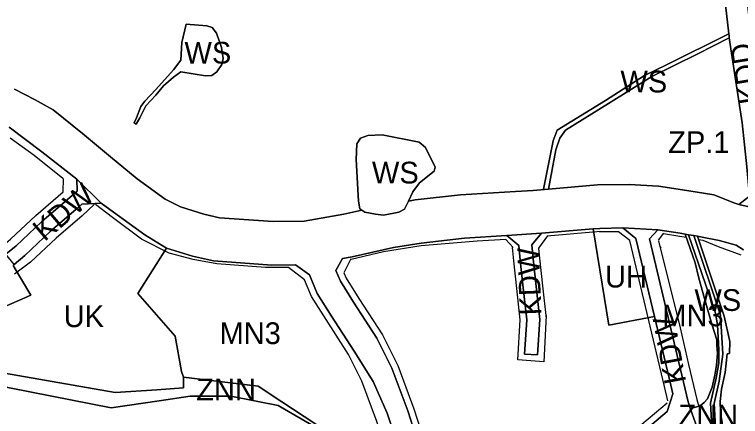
# Model space of a CAD drawing. Extents: x 7417187 to 7419415, y 5539178 to 5540826.
# Drawn here: x 7418734.7 to 7419069, y 5539661.6 to 5539846.6 of the extents above; entities that cross this region are included whole.
import ezdxf

# ---------------------------------------------------------------- set-up
doc = ezdxf.new("R2010")
doc.units = 0
for name, color, linetype in [('linie_rozgraniczajace', 7, 'Continuous'), ('linie_zabudowy_nieprzekraczalne', 7, 'Continuous'), ('oznaczenia_przeznaczen', 7, 'Continuous')]:
    doc.layers.add(name, color=color, linetype=linetype)

msp = doc.modelspace()

# ---------------------------------------------------------------- linework, layer by layer
at = {"layer": 'linie_rozgraniczajace'}
for p, q in [((7418734.61, 5539812.19), (7418744.21, 5539807.3)), ((7418744.21, 5539807.3), (7418752.52, 5539802.7)), ((7418752.52, 5539802.7), (7418766.03, 5539791.85)), ((7418747.18, 5539783.41), (7418732.26, 5539794.78)), ((7418766.03, 5539791.85), (7418778.84, 5539781.11)), ((7418763.35, 5539770.81), (7418747.18, 5539783.41)), ((7418778.84, 5539781.11), (7418791.15, 5539770.95)), ((7418774.51, 5539759.77), (7418763.35, 5539770.81)), ((7418791.15, 5539770.95), (7418804.08, 5539761.58)), ((7418980.62, 5539766.28), (7419003.17, 5539768.16)), ((7419003.17, 5539768.16), (7419017.77, 5539768.42)), ((7419017.77, 5539768.42), (7419031.26, 5539767.62)), ((7419031.26, 5539767.62), (7419044.35, 5539765.68)), ((7418940.11, 5539763.69), (7418965.45, 5539765.2)), ((7418965.45, 5539765.2), (7418973.52, 5539765.68)), ((7418973.52, 5539765.68), (7418978.79, 5539766.12)), ((7418978.79, 5539766.12), (7418980.62, 5539766.28)), ((7419044.35, 5539765.68), (7419056.75, 5539763.59)), ((7418804.08, 5539761.58), (7418811.03, 5539758.06)), ((7418914.35, 5539757.03), (7418916.12, 5539760.75)), ((7418916.12, 5539760.75), (7418919.26, 5539761.26)), ((7418919.26, 5539761.26), (7418940.11, 5539763.69)), ((7419056.75, 5539763.59), (7419066.42, 5539759.83)), ((7418780.23, 5539755.6), (7418774.51, 5539759.77)), ((7418811.03, 5539758.06), (7418821.83, 5539754.66)), ((7419066.42, 5539759.83), (7419068.31, 5539759.14)), ((7419068.31, 5539759.14), (7419081.09, 5539756.29)), ((7418794.71, 5539745.18), (7418780.23, 5539755.6)), ((7418821.83, 5539754.66), (7418829.13, 5539753.05)), ((7418868.04, 5539751.48), (7418886.3, 5539754.76)), ((7418886.3, 5539754.76), (7418894.56, 5539756.6)), ((7418894.56, 5539756.6), (7418895.99, 5539755.69)), ((7418895.99, 5539755.69), (7418900.98, 5539754.68)), ((7418900.98, 5539754.68), (7418904.59, 5539754.27)), ((7418904.59, 5539754.27), (7418911.62, 5539755.68)), ((7418911.62, 5539755.68), (7418914.35, 5539757.03)), ((7418829.13, 5539753.05), (7418853.81, 5539751.33)), ((7418853.81, 5539751.33), (7418868.04, 5539751.48)), ((7419001.16, 5539747.92), (7418977.42, 5539745.94)), ((7419004.18, 5539748.18), (7419001.16, 5539747.92)), ((7419014.82, 5539748.37), (7419004.18, 5539748.18)), ((7419030.91, 5539747.46), (7419014.82, 5539748.37)), ((7419041.22, 5539745.93), (7419030.91, 5539747.46)), ((7418804.62, 5539739.12), (7418794.71, 5539745.18)), ((7418961.45, 5539744.93), (7418941.87, 5539743.76)), ((7418977.42, 5539745.94), (7418961.45, 5539744.93)), ((7419043.55, 5539745.53), (7419041.22, 5539745.93)), ((7419045.02, 5539745.28), (7419043.55, 5539745.53)), ((7419047.5, 5539744.86), (7419045.02, 5539745.28)), ((7419049.17, 5539744.58), (7419047.5, 5539744.86)), ((7419051.4, 5539744.21), (7419049.17, 5539744.58)), ((7419059.26, 5539742.54), (7419051.4, 5539744.21)), ((7418922.01, 5539741.44), (7418909.26, 5539739.38)), ((7418941.87, 5539743.76), (7418922.01, 5539741.44)), ((7419066.99, 5539740.46), (7419059.26, 5539742.54)), ((7418816.66, 5539735.33), (7418804.62, 5539739.12)), ((7418909.26, 5539739.38), (7418890.24, 5539735.15)), ((7419070.47, 5539738.34), (7419066.99, 5539740.46)), ((7418826.26, 5539733.2), (7418816.66, 5539735.33)), ((7418885.72, 5539734.33), (7418882.61, 5539728.84)), ((7418890.24, 5539735.15), (7418885.72, 5539734.33)), ((7418853.21, 5539731.33), (7418826.26, 5539733.2)), ((7418864.01, 5539731.44), (7418853.21, 5539731.33)), ((7418870.47, 5539726.74), (7418864.01, 5539731.44)), ((7418882.61, 5539728.84), (7418884.73, 5539723.85)), ((7418874.06, 5539718.28), (7418870.47, 5539726.74)), ((7418884.73, 5539723.85), (7418890.76, 5539714.26)), ((7418880.65, 5539707.8), (7418874.06, 5539718.28)), ((7418890.76, 5539714.26), (7418901.58, 5539697.65)), ((7418891.15, 5539691.67), (7418880.65, 5539707.8)), ((7418901.58, 5539697.65), (7418908.47, 5539683.84)), ((7418899.89, 5539677.74), (7418891.15, 5539691.67)), ((7418908.47, 5539683.84), (7418915.76, 5539664.18)), ((7418906.24, 5539663.18), (7418899.89, 5539677.74)), ((7418915.76, 5539664.18), (7418920.06, 5539650.87)), ((7418910.1, 5539651.81), (7418906.24, 5539663.18))]:
    msp.add_line(p, q, dxfattribs=at)
for points in [[(7419061.66, 5539855.14), (7419063.63, 5539837.78), (7419034.92, 5539823.52), (7419024.87, 5539818.62), (7419006.8, 5539807.01), (7418984.61, 5539793.4), (7418982.8, 5539788.45), (7418978.36, 5539766.3), (7418978.79, 5539766.12), (7418973.52, 5539765.68), (7418965.45, 5539765.2), (7418940.11, 5539763.69), (7418919.26, 5539761.26), (7418916.12, 5539760.75), (7418918.11, 5539764.97), (7418921.2, 5539769.2), (7418927.98, 5539774.45), (7418928.33, 5539776.42), (7418923.97, 5539785.48), (7418921.07, 5539787.94), (7418903.96, 5539791.29), (7418897.36, 5539790.98), (7418894.02, 5539789.68), (7418892.37, 5539787.04), (7418892.01, 5539779.82), (7418893.08, 5539760.72), (7418893.7, 5539757.14), (7418894.56, 5539756.6), (7418886.3, 5539754.76), (7418868.04, 5539751.48), (7418853.81, 5539751.33), (7418829.13, 5539753.05), (7418821.83, 5539754.66), (7418811.03, 5539758.06), (7418804.08, 5539761.58), (7418791.15, 5539770.95), (7418778.84, 5539781.11), (7418766.03, 5539791.85), (7418752.52, 5539802.7), (7418744.21, 5539807.3), (7418734.61, 5539812.19)], [(7419071.59, 5539856.29), (7419073.67, 5539837.92), (7419076.8, 5539817.26), (7419079.76, 5539798.03), (7419081.88, 5539777.49), (7419082.92, 5539766.9), (7419083.42, 5539761.8), (7419083.36, 5539760.85), (7419087.96, 5539754.81), (7419081.09, 5539756.29), (7419068.31, 5539759.14), (7419073.25, 5539763.02), (7419071.93, 5539776.49), (7419069.84, 5539796.75), (7419066.92, 5539815.75), (7419063.87, 5539835.91), (7419063.76, 5539836.61), (7419063.63, 5539837.78), (7419061.66, 5539855.14)], [(7418732.26, 5539794.78), (7418747.18, 5539783.41), (7418763.35, 5539770.81), (7418763.48, 5539765.38), (7418759.1, 5539761.43), (7418747.12, 5539751.15), (7418735.44, 5539740.18), (7418730.71, 5539736.26)], [(7418920.06, 5539650.87), (7418915.76, 5539664.18), (7418908.47, 5539683.84), (7418901.58, 5539697.65), (7418890.76, 5539714.26), (7418884.73, 5539723.85), (7418882.61, 5539728.84), (7418885.72, 5539734.33), (7418890.24, 5539735.15), (7418909.26, 5539739.38), (7418922.01, 5539741.44), (7418941.87, 5539743.76), (7418961.45, 5539744.93), (7418966.91, 5539740.25), (7418967.54, 5539733.52), (7418968.92, 5539720.8), (7418970.59, 5539706.17), (7418969.57, 5539690.33), (7418975.55, 5539689.94), (7418976.62, 5539706.32), (7418974.88, 5539721.46), (7418973.51, 5539734.12), (7418972.91, 5539740.55), (7418977.42, 5539745.94), (7419001.16, 5539747.92), (7419008.35, 5539703.62), (7419029.46, 5539707.58), (7419036.97, 5539676.03), (7419037.87, 5539672.08), (7419035.19, 5539663.96), (7419023.09, 5539653.63)], [(7419023.09, 5539653.63), (7419035.19, 5539663.96), (7419037.87, 5539672.08), (7419036.97, 5539676.03), (7419029.46, 5539707.58), (7419020.89, 5539743.57), (7419014.82, 5539748.37), (7419030.91, 5539747.46), (7419027.12, 5539743.33), (7419042.81, 5539677.39), (7419044.89, 5539668.35), (7419045.89, 5539665.52), (7419049.14, 5539656.4)], [(7419049.14, 5539656.4), (7419045.89, 5539665.52), (7419046.75, 5539665.51), (7419050.45, 5539666.45), (7419052.24, 5539668.1), (7419053.83, 5539669.81), (7419056.05, 5539675.14), (7419057.26, 5539680.71), (7419057.94, 5539685.19), (7419058.5, 5539690.67), (7419058.14, 5539694.46), (7419058.1, 5539696.97), (7419055.88, 5539704.12), (7419052.45, 5539715.97), (7419049.85, 5539725.26), (7419048.08, 5539732.41), (7419043.55, 5539745.53), (7419045.02, 5539745.28), (7419057.49, 5539709.17), (7419058.46, 5539703.84), (7419059.04, 5539692.28), (7419059.02, 5539686.28), (7419057.85, 5539679.27), (7419055.16, 5539667.82), (7419055.93, 5539654.12)], [(7419057.67, 5539654.15), (7419056.87, 5539667.66), (7419059.26, 5539677.84), (7419060.96, 5539690.25), (7419059.78, 5539708.29), (7419047.5, 5539744.86), (7419049.17, 5539744.58), (7419061.52, 5539707.82), (7419064.17, 5539696.06), (7419064.03, 5539690.68), (7419062.96, 5539690.49), (7419062.02, 5539681.91), (7419060.32, 5539674.24), (7419059.62, 5539668.54), (7419059.89, 5539663.67), (7419062.14, 5539648.91)], [(7419062.14, 5539648.91), (7419059.89, 5539663.67), (7419059.62, 5539668.54), (7419060.32, 5539674.24), (7419062.02, 5539681.91), (7419062.96, 5539690.49), (7419064.03, 5539690.68), (7419064.17, 5539696.06), (7419061.52, 5539707.82), (7419049.17, 5539744.58), (7419051.4, 5539744.21), (7419059.26, 5539742.54), (7419066.99, 5539740.46), (7419070.47, 5539738.34)], [(7418734.05, 5539731.09), (7418742.1, 5539717.38), (7418736.92, 5539715.13), (7418726.22, 5539710.49)], [(7418716.69, 5539683.83), (7418781.07, 5539672.68), (7418800.26, 5539673.95), (7418812.43, 5539674.88), (7418812.55, 5539679.73), (7418846.8, 5539675.56), (7418857.8, 5539668.36), (7418872.9, 5539658.41), (7418881.51, 5539653.71), (7418890.59, 5539644.9), (7418897.27, 5539634.04), (7418892.9, 5539630.28), (7418888.03, 5539643.41), (7418871.51, 5539657.77), (7418856.13, 5539666.67), (7418834.34, 5539671.03), (7418815.62, 5539670.95), (7418801.32, 5539668.85), (7418779.1, 5539665.63), (7418723.54, 5539676.5)], [(7418723.54, 5539676.5), (7418779.1, 5539665.63), (7418801.32, 5539668.85), (7418815.62, 5539670.95), (7418834.34, 5539671.03), (7418856.13, 5539666.67), (7418871.51, 5539657.77)]]:
    msp.add_lwpolyline(points, dxfattribs=at)
for points in [[(7418830.19, 5539823.65), (7418827.84, 5539820.26), (7418825.49, 5539818.54), (7418822.57, 5539818.36), (7418811.24, 5539820.26), (7418807.88, 5539817.8), (7418803.3, 5539813.86), (7418799.81, 5539809.56), (7418795.17, 5539804.53), (7418792.33, 5539799.07), (7418790.67, 5539796.14), (7418789.75, 5539796.79), (7418790.84, 5539799.11), (7418792.81, 5539804.23), (7418794.68, 5539806.78), (7418799.71, 5539812.13), (7418807.85, 5539821.16), (7418811.21, 5539825.62), (7418811.76, 5539833.67), (7418813.64, 5539842.14), (7418823.19, 5539841.41), (7418825.64, 5539840.63), (7418827.62, 5539837.97), (7418829.94, 5539831.47), (7418830.83, 5539826.34)], [(7418830.19, 5539823.65), (7418830.83, 5539826.34), (7418829.94, 5539831.47), (7418827.62, 5539837.97), (7418825.64, 5539840.63), (7418823.19, 5539841.41), (7418813.64, 5539842.14), (7418811.76, 5539833.67), (7418811.21, 5539825.62), (7418807.85, 5539821.16), (7418799.71, 5539812.13), (7418794.68, 5539806.78), (7418792.81, 5539804.23), (7418790.84, 5539799.11), (7418789.75, 5539796.79), (7418790.67, 5539796.14), (7418792.33, 5539799.07), (7418795.17, 5539804.53), (7418799.81, 5539809.56), (7418803.3, 5539813.86), (7418807.88, 5539817.8), (7418811.24, 5539820.26), (7418822.57, 5539818.36), (7418825.49, 5539818.54), (7418827.84, 5539820.26)], [(7419063.87, 5539835.91), (7419049.32, 5539828.49), (7419028.14, 5539818.06), (7419008.25, 5539805.73), (7418988.47, 5539793.43), (7418985.78, 5539789.71), (7418983.98, 5539784.4), (7418980.62, 5539766.28), (7418978.79, 5539766.12), (7418978.36, 5539766.3), (7418982.8, 5539788.45), (7418984.61, 5539793.4), (7419006.8, 5539807.01), (7419024.87, 5539818.62), (7419034.92, 5539823.52), (7419063.63, 5539837.78), (7419063.76, 5539836.61)], [(7419068.31, 5539759.14), (7419066.42, 5539759.83), (7419056.75, 5539763.59), (7419044.35, 5539765.68), (7419031.26, 5539767.62), (7419017.77, 5539768.42), (7419003.17, 5539768.16), (7418980.62, 5539766.28), (7418983.98, 5539784.4), (7418985.78, 5539789.71), (7418988.47, 5539793.43), (7419008.25, 5539805.73), (7419028.14, 5539818.06), (7419049.32, 5539828.49), (7419063.87, 5539835.91), (7419066.92, 5539815.75), (7419069.84, 5539796.75), (7419071.93, 5539776.49), (7419073.25, 5539763.02)], [(7418916.12, 5539760.75), (7418914.35, 5539757.03), (7418911.62, 5539755.68), (7418904.59, 5539754.27), (7418900.98, 5539754.68), (7418895.99, 5539755.69), (7418894.56, 5539756.6), (7418893.7, 5539757.14), (7418893.08, 5539760.72), (7418892.01, 5539779.82), (7418892.37, 5539787.04), (7418894.02, 5539789.68), (7418897.36, 5539790.98), (7418903.96, 5539791.29), (7418921.07, 5539787.94), (7418923.97, 5539785.48), (7418928.33, 5539776.42), (7418927.98, 5539774.45), (7418921.2, 5539769.2), (7418918.11, 5539764.97)], [(7418774.51, 5539759.77), (7418765.61, 5539759.3), (7418763.11, 5539756.96), (7418751.12, 5539746.68), (7418739.41, 5539735.68), (7418734.54, 5539731.64), (7418730.71, 5539736.26), (7418735.44, 5539740.18), (7418747.12, 5539751.15), (7418759.1, 5539761.43), (7418763.48, 5539765.38), (7418763.35, 5539770.81)], [(7418804.62, 5539739.12), (7418791.51, 5539718.25), (7418808.62, 5539698.53), (7418811.52, 5539682.26), (7418812.55, 5539679.73), (7418812.43, 5539674.88), (7418800.26, 5539673.95), (7418781.07, 5539672.68), (7418716.69, 5539683.83), (7418704.53, 5539706.68), (7418719.32, 5539708.39), (7418725.09, 5539710), (7418726.22, 5539710.49), (7418736.92, 5539715.13), (7418742.1, 5539717.38), (7418734.05, 5539731.09), (7418734.54, 5539731.64), (7418739.41, 5539735.68), (7418751.12, 5539746.68), (7418763.11, 5539756.96), (7418765.61, 5539759.3), (7418774.51, 5539759.77), (7418780.23, 5539755.6), (7418794.71, 5539745.18)], [(7419029.46, 5539707.58), (7419008.35, 5539703.62), (7419001.16, 5539747.92), (7419004.18, 5539748.18), (7419014.82, 5539748.37), (7419020.89, 5539743.57)], [(7419043.55, 5539745.53), (7419048.08, 5539732.41), (7419049.85, 5539725.26), (7419052.45, 5539715.97), (7419055.88, 5539704.12), (7419058.1, 5539696.97), (7419058.14, 5539694.46), (7419058.5, 5539690.67), (7419057.94, 5539685.19), (7419057.26, 5539680.71), (7419056.05, 5539675.14), (7419053.83, 5539669.81), (7419052.24, 5539668.1), (7419050.45, 5539666.45), (7419046.75, 5539665.51), (7419045.89, 5539665.52), (7419044.89, 5539668.35), (7419042.81, 5539677.39), (7419027.12, 5539743.33), (7419030.91, 5539747.46), (7419041.22, 5539745.93)], [(7418961.45, 5539744.93), (7418977.42, 5539745.94), (7418972.91, 5539740.55), (7418973.51, 5539734.12), (7418974.88, 5539721.46), (7418976.62, 5539706.32), (7418975.55, 5539689.94), (7418969.57, 5539690.33), (7418970.59, 5539706.17), (7418968.92, 5539720.8), (7418967.54, 5539733.52), (7418966.91, 5539740.25)], [(7419047.5, 5539744.86), (7419059.78, 5539708.29), (7419060.96, 5539690.25), (7419059.26, 5539677.84), (7419056.87, 5539667.66), (7419057.67, 5539654.15), (7419055.93, 5539654.12), (7419055.16, 5539667.82), (7419057.85, 5539679.27), (7419059.02, 5539686.28), (7419059.04, 5539692.28), (7419058.46, 5539703.84), (7419057.49, 5539709.17), (7419045.02, 5539745.28)], [(7418897.27, 5539634.04), (7418890.59, 5539644.9), (7418881.51, 5539653.71), (7418872.9, 5539658.41), (7418857.8, 5539668.36), (7418846.8, 5539675.56), (7418812.55, 5539679.73), (7418811.52, 5539682.26), (7418808.62, 5539698.53), (7418791.51, 5539718.25), (7418804.62, 5539739.12), (7418816.66, 5539735.33), (7418826.26, 5539733.2), (7418853.21, 5539731.33), (7418864.01, 5539731.44), (7418870.47, 5539726.74), (7418874.06, 5539718.28), (7418880.65, 5539707.8), (7418891.15, 5539691.67), (7418899.89, 5539677.74), (7418906.24, 5539663.18), (7418910.1, 5539651.81), (7418909.02, 5539645.17), (7418902.92, 5539638.89)]]:
    msp.add_lwpolyline(points, close=True, dxfattribs=at)
at = {"layer": 'linie_zabudowy_nieprzekraczalne'}
for points in [[(7418756.91, 5539771.1), (7418743.65, 5539781.72), (7418732.71, 5539789.72)], [(7418757.07, 5539764.94), (7418757.23, 5539771.09)], [(7418726.18, 5539737.71), (7418732.79, 5539743.18), (7418744.45, 5539754.13), (7418757.07, 5539764.94)], [(7418771.36, 5539759.21), (7418765.78, 5539753.99), (7418753.8, 5539743.71), (7418742.06, 5539732.68), (7418734.7, 5539727.15)], [(7418860.92, 5539730.16), (7418850.26, 5539730.21), (7418827.85, 5539731.87), (7418816.89, 5539733.87), (7418805.87, 5539736.86), (7418793.21, 5539743.27), (7418779.71, 5539753.2), (7418771.98, 5539759.13)], [(7418980.17, 5539744.75), (7418976.05, 5539739.14)], [(7419004.52, 5539746.7), (7418979.93, 5539744.61)], [(7419012.82, 5539746.67), (7419004, 5539746.67)], [(7419018.05, 5539742.58), (7419012.88, 5539746.67)], [(7419033.62, 5539745.95), (7419031.15, 5539742.81)], [(7419041.07, 5539744.44), (7419033.57, 5539745.63)], [(7419044.11, 5539743.92), (7419040.91, 5539744.46)], [(7418960.89, 5539743.02), (7418947.69, 5539742.23), (7418922.02, 5539740.23), (7418904.55, 5539737.41), (7418889.7, 5539733.93)], [(7418964.32, 5539739.38), (7418960.89, 5539743.02)], [(7419035.53, 5539668.9), (7419034.05, 5539675.35), (7419018.05, 5539742.58)], [(7419031.22, 5539742.51), (7419041.23, 5539702.43), (7419045.06, 5539685.49), (7419048.9, 5539669.39), (7419049.82, 5539666.29)], [(7419051.81, 5539742.62), (7419049.72, 5539742.97)], [(7419058.96, 5539739.67), (7419051.81, 5539742.62)], [(7418966.44, 5539687.77), (7418967.59, 5539706.1), (7418965.94, 5539720.47), (7418964.56, 5539733.22), (7418963.99, 5539739.35)], [(7418976.05, 5539739.14), (7418976.5, 5539734.4)], [(7419032.46, 5539739.14), (7419032.24, 5539739.75)], [(7419069.31, 5539735.92), (7419058.96, 5539739.67)], [(7418889.63, 5539734.25), (7418886.35, 5539727.74)], [(7418976.49, 5539734.45), (7418977.86, 5539721.78)], [(7418868.17, 5539724.49), (7418860.92, 5539730.16)], [(7418886.35, 5539727.74), (7418887.4, 5539725.25), (7418893.29, 5539715.88), (7418904.19, 5539699.14), (7418911.22, 5539685.04), (7418918.6, 5539665.17), (7418921.96, 5539654.75)], [(7418904.83, 5539649.22), (7418901.59, 5539659.27), (7418894.69, 5539677.87), (7418888.54, 5539690.18), (7418878.13, 5539706.18), (7418871.39, 5539716.89), (7418868.17, 5539724.49)], [(7418977.86, 5539721.81), (7418979.59, 5539706.75)], [(7418979.58, 5539708.17), (7418978.48, 5539686.75)], [(7418978.48, 5539686.75), (7418966.44, 5539687.77)], [(7419013.88, 5539626.86), (7419015.52, 5539633.27), (7419016.34, 5539638.44), (7419018.2, 5539651.08), (7419020.74, 5539655.57), (7419035.2, 5539667.91)]]:
    msp.add_lwpolyline(points, dxfattribs=at)

# ---------------------------------------------------------------- texts
at = {"layer": 'oznaczenia_przeznaczen'}
for s, p in [('WS', (7418812.94, 5539824.03)), ('WS', (7419013.73, 5539810.74)), ('ZP.1', (7419035.73, 5539782.87)), ('WS', (7418899.29, 5539768.85)), ('UH', (7419006.64, 5539720.97)), ('WS', (7419047.81, 5539710.2)), ('UK', (7418757.32, 5539702.76)), ('MN3', (7419033.03, 5539703.15)), ('MN3', (7418829.07, 5539694.94)), ('ZNN', (7418818.35, 5539669.03)), ('ZNN', (7419040.44, 5539657.13))]:
    msp.add_text(s, height=10, dxfattribs=at).set_placement(p)
for s, rotation, p in [('KDD', 99.2243, (7419078.58, 5539806.31)), ('KDW', 40.345, (7418748.44, 5539741.83)), ('KDW', 92.2906, (7418977.42, 5539708.33)), ('KDW', 100.3832, (7419044.04, 5539677.58))]:
    msp.add_text(s, height=10, rotation=rotation, dxfattribs=at).set_placement(p)

doc.saveas('drawing.dxf')
